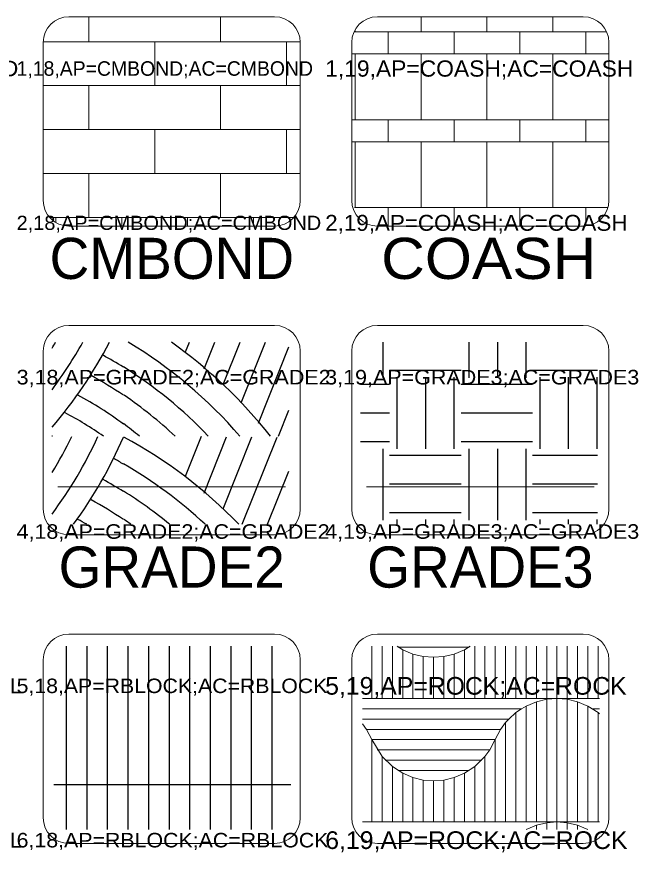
# Model space of a CAD drawing. Extents: x 95935 to 95946.4, y 95971.2 to 95974.7.
# Drawn here: x 95945.234 to 95946.443, y 95973.108 to 95974.732 of the extents above; entities that cross this region are included whole.
import ezdxf
from ezdxf.enums import TextEntityAlignment as Align

# ---------------------------------------------------------------- set-up
doc = ezdxf.new("R2010")
doc.units = 0
doc.header["$LTSCALE"] = 0.013
for name, color, linetype, lineweight in [('1', 7, 'Continuous', 13), ('25', 7, 'Continuous', 13), ('6', 7, 'Continuous', 13), ('63', 7, 'Continuous', 13)]:
    doc.layers.add(name, color=color, linetype=linetype, lineweight=lineweight)
doc.layers.add('20', color=7, linetype='Continuous')

msp = doc.modelspace()

# ---------------------------------------------------------------- linework, layer by layer
at = {"layer": '1'}
for p, q in [((95945.3357, 95974.7318), (95945.7357, 95974.7318)), ((95945.9357, 95974.7318), (95946.3357, 95974.7318)), ((95945.2857, 95974.3747), (95945.2857, 95974.6818)), ((95945.7857, 95974.6818), (95945.7857, 95974.3747)), ((95945.8857, 95974.3747), (95945.8857, 95974.6818)), ((95946.3857, 95974.6818), (95946.3857, 95974.3747)), ((95945.7357, 95974.3247), (95945.3357, 95974.3247)), ((95946.3357, 95974.3247), (95945.9357, 95974.3247)), ((95945.3357, 95974.1318), (95945.7357, 95974.1318)), ((95945.9357, 95974.1318), (95946.3357, 95974.1318)), ((95945.2857, 95973.7747), (95945.2857, 95974.0818)), ((95945.7857, 95974.0818), (95945.7857, 95973.7747)), ((95945.8857, 95973.7747), (95945.8857, 95974.0818)), ((95946.3857, 95974.0818), (95946.3857, 95973.7747)), ((95945.7357, 95973.7247), (95945.3357, 95973.7247)), ((95946.3357, 95973.7247), (95945.9357, 95973.7247)), ((95945.3357, 95973.5318), (95945.7357, 95973.5318)), ((95945.9357, 95973.5318), (95946.3357, 95973.5318)), ((95945.2857, 95973.1747), (95945.2857, 95973.4818)), ((95945.7857, 95973.4818), (95945.7857, 95973.1747)), ((95945.8857, 95973.1747), (95945.8857, 95973.4818)), ((95946.3857, 95973.4818), (95946.3857, 95973.1747)), ((95945.7357, 95973.1247), (95945.3357, 95973.1247)), ((95946.3357, 95973.1247), (95945.9357, 95973.1247))]:
    msp.add_line(p, q, dxfattribs=at)
for centre, start, end in [((95945.3357, 95974.6818), 90, 180), ((95945.7357, 95974.6818), 0, 90), ((95945.9357, 95974.6818), 90, 180), ((95946.3357, 95974.6818), 0, 90), ((95945.3357, 95974.3747), 180, 270), ((95945.7357, 95974.3747), 270, 0), ((95945.9357, 95974.3747), 180, 270), ((95946.3357, 95974.3747), 270, 0), ((95945.3357, 95974.0818), 90, 180), ((95945.7357, 95974.0818), 0, 90), ((95945.9357, 95974.0818), 90, 180), ((95946.3357, 95974.0818), 0, 90), ((95945.3357, 95973.7747), 180, 270), ((95945.7357, 95973.7747), 270, 0), ((95945.9357, 95973.7747), 180, 270), ((95946.3357, 95973.7747), 270, 0), ((95945.3357, 95973.4818), 90, 180), ((95945.7357, 95973.4818), 0, 90), ((95945.9357, 95973.4818), 90, 180), ((95946.3357, 95973.4818), 0, 90), ((95945.3357, 95973.1747), 180, 270), ((95945.7357, 95973.1747), 270, 0), ((95945.9357, 95973.1747), 180, 270), ((95946.3357, 95973.1747), 270, 0)]:
    msp.add_arc(centre, 0.05, start, end, dxfattribs=at)
at = {"layer": '25'}
for p, q in [((95945.7569, 95973.8178), (95945.3141, 95973.8178)), ((95946.3569, 95973.8178), (95945.9141, 95973.8178))]:
    msp.add_line(p, q, dxfattribs=at)
at = {"layer": '6'}
for p, q in [((95945.3746, 95974.6831), (95945.3746, 95974.7318)), ((95945.6306, 95974.6831), (95945.6306, 95974.7318)), ((95946.0207, 95974.7021), (95946.0207, 95974.7318)), ((95946.1487, 95974.7021), (95946.1487, 95974.7318)), ((95946.2767, 95974.7021), (95946.2767, 95974.7318)), ((95945.8907, 95974.7021), (95946.3811, 95974.7021)), ((95945.8927, 95974.7021), (95945.8927, 95974.7041)), ((95945.9567, 95974.6594), (95945.9567, 95974.7021)), ((95946.0847, 95974.6594), (95946.0847, 95974.7021)), ((95946.2127, 95974.6594), (95946.2127, 95974.7021)), ((95946.3407, 95974.6594), (95946.3407, 95974.7021)), ((95945.286, 95974.6831), (95945.7854, 95974.6831)), ((95945.5026, 95974.5978), (95945.5026, 95974.6831)), ((95945.7586, 95974.5978), (95945.7586, 95974.6831)), ((95945.8857, 95974.6594), (95946.3857, 95974.6594)), ((95945.8927, 95974.5314), (95945.8927, 95974.6594)), ((95946.0207, 95974.5314), (95946.0207, 95974.6594)), ((95946.1487, 95974.5314), (95946.1487, 95974.6594)), ((95946.2767, 95974.5314), (95946.2767, 95974.6594)), ((95945.2857, 95974.5978), (95945.7857, 95974.5978)), ((95945.3746, 95974.5124), (95945.3746, 95974.5978)), ((95945.6306, 95974.5124), (95945.6306, 95974.5978)), ((95945.8857, 95974.5314), (95946.3857, 95974.5314)), ((95945.9567, 95974.4888), (95945.9567, 95974.5314)), ((95946.0847, 95974.4888), (95946.0847, 95974.5314)), ((95946.2127, 95974.4888), (95946.2127, 95974.5314)), ((95946.3407, 95974.4888), (95946.3407, 95974.5314)), ((95945.2857, 95974.5124), (95945.7857, 95974.5124)), ((95945.5026, 95974.4271), (95945.5026, 95974.5124)), ((95945.7586, 95974.4271), (95945.7586, 95974.5124)), ((95945.8857, 95974.4888), (95946.3857, 95974.4888)), ((95945.8927, 95974.3608), (95945.8927, 95974.4888)), ((95946.0207, 95974.3608), (95946.0207, 95974.4888)), ((95946.1487, 95974.3608), (95946.1487, 95974.4888)), ((95946.2767, 95974.3608), (95946.2767, 95974.4888)), ((95945.2857, 95974.4271), (95945.7857, 95974.4271)), ((95945.3746, 95974.3418), (95945.3746, 95974.4271)), ((95945.6306, 95974.3418), (95945.6306, 95974.4271)), ((95945.8914, 95974.3608), (95946.3829, 95974.3608)), ((95945.9567, 95974.3247), (95945.9567, 95974.3608)), ((95946.0847, 95974.3247), (95946.0847, 95974.3608)), ((95946.2127, 95974.3247), (95946.2127, 95974.3608)), ((95946.3407, 95974.3257), (95946.3407, 95974.3608)), ((95945.2993, 95974.3418), (95945.7728, 95974.3418)), ((95945.3106, 95974.3325), (95945.3106, 95974.3418)), ((95945.4386, 95974.3247), (95945.4386, 95974.3418)), ((95945.5666, 95974.3247), (95945.5666, 95974.3418)), ((95945.6946, 95974.3247), (95945.6946, 95974.3418)), ((95945.9248, 95973.5082), (95945.9248, 95973.4065)), ((95945.9448, 95973.5082), (95945.9448, 95973.4065)), ((95945.9648, 95973.5082), (95945.9648, 95973.4065)), ((95945.9755, 95973.5065), (95946.1141, 95973.5065)), ((95945.9848, 95973.5012), (95945.9848, 95973.4065)), ((95946.1048, 95973.5012), (95946.1048, 95973.4065)), ((95946.1248, 95973.5082), (95946.1248, 95973.4065)), ((95946.1448, 95973.5082), (95946.1448, 95973.4065)), ((95946.1648, 95973.5082), (95946.1648, 95973.4065)), ((95946.1848, 95973.5082), (95946.1848, 95973.4065)), ((95946.2048, 95973.5082), (95946.2048, 95973.4065)), ((95946.2248, 95973.5082), (95946.2248, 95973.4065)), ((95946.2448, 95973.5082), (95946.2448, 95973.4065)), ((95946.2648, 95973.5082), (95946.2648, 95973.4065)), ((95946.2848, 95973.5082), (95946.2848, 95973.1517)), ((95946.3048, 95973.5082), (95946.3048, 95973.4065)), ((95946.3248, 95973.5082), (95946.3248, 95973.4065)), ((95946.3448, 95973.5082), (95946.3448, 95973.4065)), ((95946.3648, 95973.5082), (95946.3648, 95973.4065)), ((95946.0048, 95973.4928), (95946.0048, 95973.4065)), ((95946.0248, 95973.488), (95946.0248, 95973.4065)), ((95946.0448, 95973.4865), (95946.0448, 95973.4065)), ((95946.0648, 95973.488), (95946.0648, 95973.4065)), ((95946.0848, 95973.4928), (95946.0848, 95973.4065)), ((95945.9066, 95973.4065), (95946.3672, 95973.4065)), ((95946.2448, 95973.4002), (95946.2448, 95973.1665)), ((95946.2648, 95973.405), (95946.2648, 95973.1665)), ((95946.3048, 95973.405), (95946.3048, 95973.1665)), ((95946.3248, 95973.4002), (95946.3248, 95973.1665)), ((95945.9248, 95973.3865), (95945.9066, 95973.3865)), ((95945.9248, 95973.3865), (95946.2155, 95973.3865)), ((95946.2248, 95973.3918), (95946.2248, 95973.1665)), ((95946.3448, 95973.3918), (95946.3448, 95973.1665)), ((95946.3672, 95973.3865), (95946.3541, 95973.3865)), ((95946.2048, 95973.379), (95946.2048, 95973.1665)), ((95946.3648, 95973.379), (95946.3648, 95973.1665)), ((95945.9248, 95973.3665), (95945.9066, 95973.3665)), ((95945.9248, 95973.3665), (95946.191, 95973.3665)), ((95946.1848, 95973.3596), (95946.1848, 95973.1665)), ((95945.9248, 95973.3465), (95945.9143, 95973.3465)), ((95945.9248, 95973.3465), (95946.1753, 95973.3465)), ((95945.9248, 95973.3265), (95946.1648, 95973.3265)), ((95945.9248, 95973.3265), (95945.9248, 95973.1665)), ((95946.1648, 95973.3265), (95946.1648, 95973.1665)), ((95945.9353, 95973.3065), (95946.1543, 95973.3065)), ((95945.9448, 95973.2934), (95945.9448, 95973.1665)), ((95945.951, 95973.2865), (95946.1386, 95973.2865)), ((95946.1448, 95973.2934), (95946.1448, 95973.1665)), ((95945.9648, 95973.274), (95945.9648, 95973.1665)), ((95946.1248, 95973.274), (95946.1248, 95973.1665)), ((95945.9755, 95973.2665), (95946.1141, 95973.2665)), ((95945.9848, 95973.2612), (95945.9848, 95973.1665)), ((95946.1048, 95973.2612), (95946.1048, 95973.1665)), ((95946.0048, 95973.2528), (95946.0048, 95973.1665)), ((95946.0248, 95973.248), (95946.0248, 95973.1665)), ((95946.0448, 95973.2465), (95946.0448, 95973.1665)), ((95946.0648, 95973.248), (95946.0648, 95973.1665)), ((95946.0848, 95973.2528), (95946.0848, 95973.1665)), ((95945.9066, 95973.1665), (95946.3672, 95973.1665)), ((95946.2448, 95973.1602), (95946.2448, 95973.1517)), ((95946.2648, 95973.165), (95946.2648, 95973.1517)), ((95946.3048, 95973.165), (95946.3048, 95973.1517)), ((95946.3248, 95973.1602), (95946.3248, 95973.1517))]:
    msp.add_line(p, q, dxfattribs=at)
at = {"layer": '6', "lineweight": 25}
for p, q in [((95945.5626, 95974.0801), (95945.5702, 95974.099)), ((95945.5987, 95974.0473), (95945.6194, 95974.099)), ((95945.6357, 95974.0167), (95945.6686, 95974.099)), ((95945.6708, 95973.9813), (95945.7179, 95974.099)), ((95945.9465, 95974.099), (95945.9465, 95974.0301)), ((95946.1133, 95974.099), (95946.1133, 95974.0301)), ((95946.1689, 95974.099), (95946.1689, 95974.0301)), ((95946.2245, 95974.099), (95946.2245, 95974.0301)), ((95945.7043, 95973.942), (95945.7636, 95974.0902)), ((95945.9594, 95974.045), (95946.0983, 95974.045)), ((95946.2373, 95974.045), (95946.3636, 95974.045)), ((95945.9029, 95974.0172), (95945.9594, 95974.0172)), ((95945.9733, 95974.0311), (95945.9733, 95973.8921)), ((95946.0289, 95974.0311), (95946.0289, 95973.8921)), ((95946.0844, 95974.0311), (95946.0844, 95973.8921)), ((95946.0983, 95974.0172), (95946.2373, 95974.0172)), ((95946.2512, 95974.0311), (95946.2512, 95973.8921)), ((95946.3068, 95974.0311), (95946.3068, 95973.8921)), ((95946.3624, 95974.0311), (95946.3624, 95973.8921)), ((95945.7432, 95973.9162), (95945.7636, 95973.9672)), ((95945.9029, 95973.9616), (95945.9594, 95973.9616)), ((95946.0983, 95973.9616), (95946.2373, 95973.9616)), ((95945.5626, 95973.8385), (95945.5937, 95973.9162)), ((95945.5987, 95973.8057), (95945.6424, 95973.915)), ((95945.6357, 95973.7751), (95945.6917, 95973.9151)), ((95945.6729, 95973.7451), (95945.7408, 95973.9147)), ((95945.9029, 95973.906), (95945.9594, 95973.906)), ((95946.0983, 95973.906), (95946.2373, 95973.906)), ((95945.9465, 95973.8921), (95945.9465, 95973.7531)), ((95946.1133, 95973.8921), (95946.1133, 95973.7531)), ((95946.1689, 95973.8921), (95946.1689, 95973.7531)), ((95946.2245, 95973.8921), (95946.2245, 95973.7531)), ((95945.9594, 95973.8792), (95946.0983, 95973.8792)), ((95946.2373, 95973.8792), (95946.3636, 95973.8792)), ((95945.7222, 95973.7451), (95945.7636, 95973.8486)), ((95945.9594, 95973.8236), (95946.0983, 95973.8236)), ((95946.2373, 95973.8236), (95946.3636, 95973.8236)), ((95945.9594, 95973.768), (95946.0983, 95973.768)), ((95946.2373, 95973.768), (95946.3636, 95973.768)), ((95945.9733, 95973.7541), (95945.9733, 95973.7451)), ((95946.0289, 95973.7541), (95946.0289, 95973.7451)), ((95946.0844, 95973.7541), (95946.0844, 95973.7451)), ((95946.2512, 95973.7541), (95946.2512, 95973.7451)), ((95946.3068, 95973.7541), (95946.3068, 95973.7451)), ((95946.3624, 95973.7541), (95946.3624, 95973.7451)), ((95945.3304, 95973.5082), (95945.3304, 95973.1517)), ((95945.3704, 95973.5082), (95945.3704, 95973.1517)), ((95945.4104, 95973.5082), (95945.4104, 95973.1517)), ((95945.4504, 95973.5082), (95945.4504, 95973.1517)), ((95945.4904, 95973.5082), (95945.4904, 95973.1517)), ((95945.5304, 95973.5082), (95945.5304, 95973.1517)), ((95945.5704, 95973.5082), (95945.5704, 95973.1517)), ((95945.6104, 95973.5082), (95945.6104, 95973.1517)), ((95945.6504, 95973.5082), (95945.6504, 95973.1517)), ((95945.6904, 95973.5082), (95945.6904, 95973.1517)), ((95945.7304, 95973.5082), (95945.7304, 95973.1517)), ((95945.3066, 95973.2396), (95945.7672, 95973.2396))]:
    msp.add_line(p, q, dxfattribs=at)
at = {"layer": '6'}
for points in [[(95945.9739, 95973.5082), (95945.9848, 95973.5012), (95946.0048, 95973.4928), (95946.0248, 95973.488), (95946.0448, 95973.4865), (95946.0648, 95973.488), (95946.0848, 95973.4928), (95946.1048, 95973.5012), (95946.1157, 95973.5082)], [(95945.9248, 95973.3265), (95945.9448, 95973.2934), (95945.9648, 95973.274), (95945.9848, 95973.2612), (95946.0048, 95973.2528), (95946.0248, 95973.248), (95946.0448, 95973.2465), (95946.0648, 95973.248), (95946.0848, 95973.2528), (95946.1048, 95973.2612), (95946.1248, 95973.274), (95946.1448, 95973.2934), (95946.1543, 95973.3065), (95946.1648, 95973.3265), (95946.1753, 95973.3465), (95946.1848, 95973.3596), (95946.191, 95973.3665), (95946.2048, 95973.379), (95946.2155, 95973.3865), (95946.2248, 95973.3918), (95946.2448, 95973.4002), (95946.2648, 95973.405), (95946.2848, 95973.4065), (95946.3048, 95973.405), (95946.3248, 95973.4002), (95946.3448, 95973.3918), (95946.3648, 95973.379), (95946.3672, 95973.3768)], [(95945.9066, 95973.3571), (95945.9143, 95973.3465), (95945.9248, 95973.3265)], [(95946.2246, 95973.1517), (95946.2248, 95973.1518), (95946.2448, 95973.1602), (95946.2648, 95973.165), (95946.2848, 95973.1665), (95946.3048, 95973.165), (95946.3248, 95973.1602), (95946.3448, 95973.1518), (95946.345, 95973.1517)]]:
    msp.add_lwpolyline(points, dxfattribs=at)
at = {"layer": '6', "lineweight": 25}
for centre, radius, start, end in [((95944.6472, 95974.4974), 0.819, 323.1912, 330.8901), ((95944.6472, 95974.4974), 0.7733, 327.9918, 328.9861), ((95944.6472, 95974.4974), 0.8647, 319.3156, 332.5634), ((95945.0029, 95973.3454), 0.8767, 40.6229, 59.2641), ((95945.0029, 95973.3454), 0.9225, 38.2295, 54.7794), ((95945.0019, 95973.3454), 0.831, 58.0417, 61.212), ((95945.0029, 95973.3454), 0.831, 43.3846, 58.122), ((95945.0019, 95973.3454), 0.7853, 55.9364, 61.292), ((95945.0019, 95973.3454), 0.7396, 53.5064, 61.6348), ((95945.0029, 95973.3454), 0.7853, 46.6253, 55.9152), ((95945.0019, 95973.3454), 0.6976, 54.9167, 62.1105), ((95945.0029, 95973.3454), 0.7396, 50.5164, 53.6057), ((95945.0019, 95973.3454), 0.6459, 62.1053, 62.2193), ((95944.6472, 95974.2558), 0.7733, 327.9918, 333.9054), ((95944.6472, 95974.2558), 0.819, 323.1912, 335.4468), ((95944.6472, 95974.2558), 0.8647, 323.7959, 336.7608), ((95945.0029, 95973.1038), 0.9225, 44.0411, 61.5207), ((95945.0019, 95973.1038), 0.8767, 59.8873, 61.3065), ((95945.0029, 95973.1038), 0.8767, 47.0056, 59.9366), ((95945.0019, 95973.1038), 0.831, 58.0417, 61.212), ((95945.0029, 95973.1038), 0.831, 50.5028, 58.122), ((95945.0019, 95973.1038), 0.7853, 55.9364, 61.292), ((95945.0019, 95973.1038), 0.7396, 60.1174, 61.6348), ((95945.0029, 95973.1038), 0.7853, 54.7434, 55.9152)]:
    msp.add_arc(centre, radius, start, end, dxfattribs=at)

# ---------------------------------------------------------------- texts
at = {"layer": '20'}
for s, p in [('CMBOND', (95945.5359, 95974.222)), ('GRADE2', (95945.5357, 95973.622)), ('GRADE3', (95946.1358, 95973.622))]:
    msp.add_text(s, height=0.08, dxfattribs=at).set_placement(p, align=Align.CENTER)
at = {"layer": '20', "width": 1.1}
msp.add_text(' COASH', height=0.08, dxfattribs=at).set_placement((95946.1358, 95974.222), align=Align.CENTER)
at = {"layer": '63'}
for s, height, width, p in [('1,17,AP=CLGRID;AC=CLGRID', 0.0308, 1.05, (95944.6341, 95974.6157)), ('1,19,AP=COASH;AC=COASH', 0.0316, 1.05, (95945.8341, 95974.6153)), ('2,18,AP=CMBOND;AC=CMBOND', 0.0276, 1.05, (95945.2341, 95974.3173)), ('2,19,AP=COASH;AC=COASH', 0.031, 1.05, (95945.8341, 95974.3156)), ('3,18,AP=GRADE2;AC=GRADE2', 0.0284, 1.1, (95945.2341, 95974.0169)), ('3,19,AP=GRADE3;AC=GRADE3', 0.0284, 1.1, (95945.8341, 95974.0169)), ('4,18,AP=GRADE2;AC=GRADE2', 0.0283, 1.1, (95945.2341, 95973.7169)), ('4,19,AP=GRADE3;AC=GRADE3', 0.0284, 1.1, (95945.8341, 95973.7169)), ('5,19,AP=ROCK;AC=ROCK', 0.0343, 1.05, (95945.8341, 95973.4139)), ('5,17,AP=RANRBL;AC=RANRBL', 0.0286, 1.1, (95944.6341, 95973.4168)), ('5,18,AP=RBLOCK;AC=RBLOCK', 0.0281, 1.1, (95945.2341, 95973.417)), ('6,17,AP=RANRBL;AC=RANRBL', 0.0286, 1.1, (95944.6341, 95973.1168)), ('6,18,AP=RBLOCK;AC=RBLOCK', 0.0282, 1.1, (95945.2341, 95973.117)), ('6,19,AP=ROCK;AC=ROCK', 0.0344, 1.05, (95945.8341, 95973.1139))]:
    msp.add_text(s, height=height, dxfattribs=dict(at, width=width)).set_placement(p)
msp.add_text('1,18,AP=CMBOND;AC=CMBOND', height=0.0282, dxfattribs=at).set_placement((95945.2341, 95974.617))

doc.saveas('drawing.dxf')
